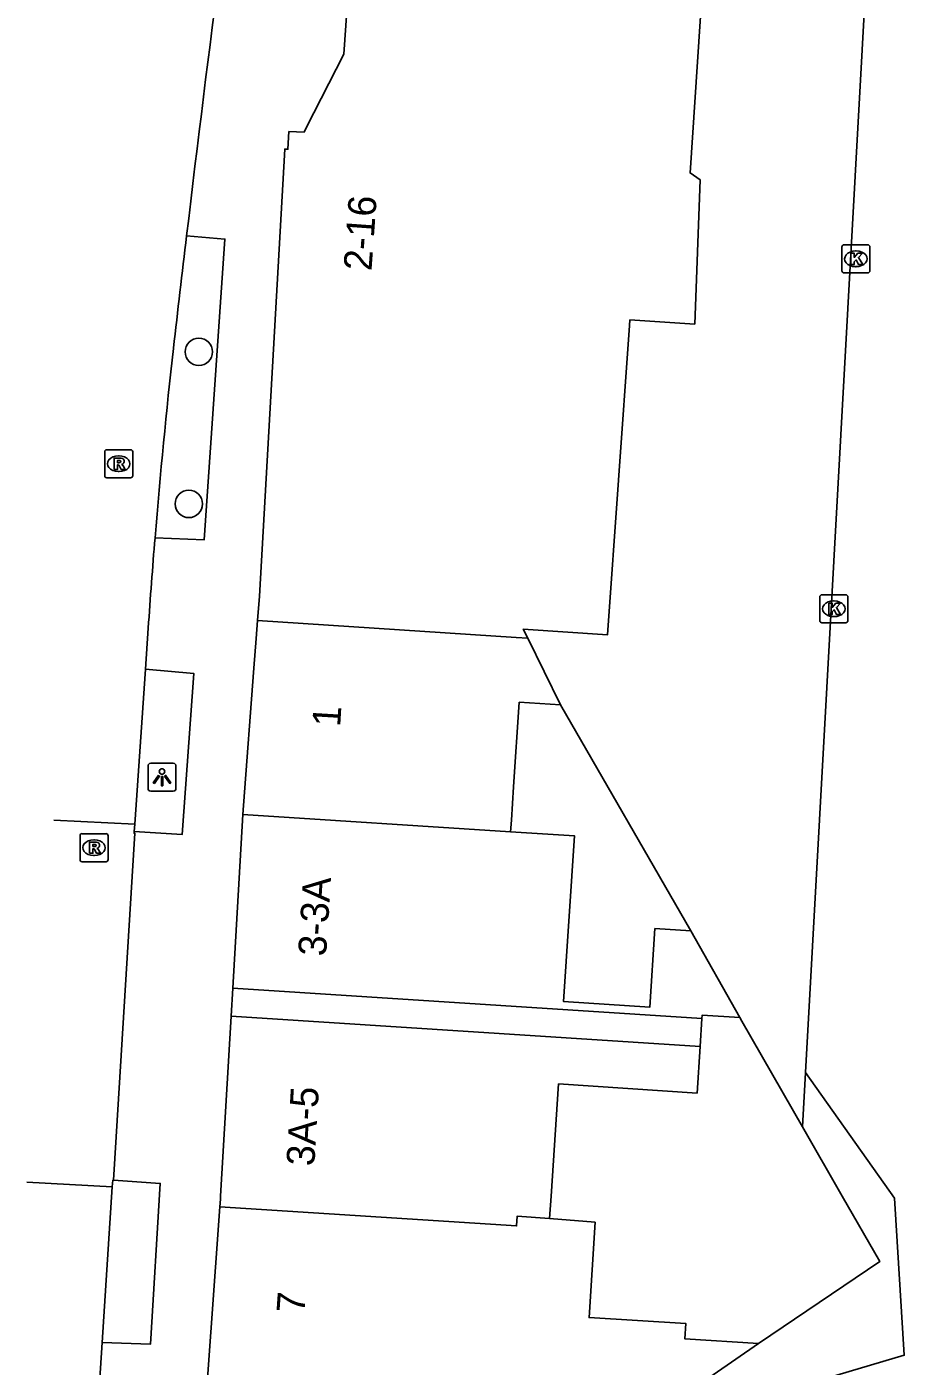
# Model space of a CAD drawing. Extents: x 161801 to 162379, y 382315 to 382832.
# Drawn here: x 161869.18 to 161900.49, y 382743.94 to 382791.72 of the extents above; entities that cross this region are included whole.
import ezdxf

# ---------------------------------------------------------------- set-up
doc = ezdxf.new("R2010")
doc.units = 0
for name, color, linetype in [('IMGEO_Boom', 7, 'Continuous'), ('IMGEO_Kolk', 7, 'Continuous'), ('IMGEO_Lichtpunt', 7, 'Continuous'), ('IMGEO_Pand', 7, 'Continuous'), ('IMGEO_Pand_nummerreeks', 7, 'Continuous'), ('IMGEO_Pand_overbouw', 7, 'Continuous'), ('IMGEO_Parkeervlak_open', 7, 'Continuous'), ('IMGEO_Rijbaan_lokaal_gesloten', 7, 'Continuous'), ('IMGEO_Rijbaan_lokaal_open', 7, 'Continuous'), ('IMGEO_Rioolput', 7, 'Continuous'), ('IMGEO_Voetpad_open', 7, 'Continuous')]:
    doc.layers.add(name, color=color, linetype=linetype)

msp = doc.modelspace()

# ---------------------------------------------------------------- linework, layer by layer
at = {"layer": 'IMGEO_Boom'}
for centre in [(161875.32, 382780.122), (161874.962, 382774.696)]:
    msp.add_circle(centre, 0.489, dxfattribs=at)
at = {"layer": 'IMGEO_Kolk'}
for p, q in [((161898.264, 382783.013), (161898.264, 382783.865)), ((161898.339, 382783.939), (161899.191, 382783.939)), ((161898.752, 382783.719), (161898.777, 382783.719)), ((161899.265, 382783.865), (161899.265, 382783.013)), ((161898.775, 382783.159), (161898.75, 382783.159)), ((161899.191, 382782.939), (161898.339, 382782.939)), ((161897.477, 382770.528), (161897.477, 382771.38)), ((161897.552, 382771.454), (161898.404, 382771.454)), ((161897.965, 382771.234), (161897.99, 382771.234)), ((161898.478, 382771.38), (161898.478, 382770.528)), ((161897.988, 382770.674), (161897.963, 382770.674)), ((161898.404, 382770.454), (161897.552, 382770.454))]:
    msp.add_line(p, q, dxfattribs=at)
for points in [[(161898.264, 382783.013), (161898.264, 382783.865)], [(161898.339, 382783.939), (161899.191, 382783.939)], [(161898.585, 382783.639), (161898.708, 382783.639), (161898.708, 382783.488), (161898.838, 382783.639), (161899.002, 382783.639), (161898.856, 382783.488), (161899.009, 382783.239), (161898.857, 382783.239), (161898.772, 382783.403), (161898.708, 382783.336), (161898.708, 382783.239), (161898.585, 382783.239), (161898.585, 382783.639)], [(161899.265, 382783.865), (161899.265, 382783.013)], [(161899.191, 382782.939), (161898.339, 382782.939)], [(161897.477, 382770.528), (161897.477, 382771.38)], [(161897.552, 382771.454), (161898.404, 382771.454)], [(161897.798, 382771.154), (161897.921, 382771.154), (161897.921, 382771.003), (161898.051, 382771.154), (161898.215, 382771.154), (161898.069, 382771.003), (161898.222, 382770.754), (161898.07, 382770.754), (161897.985, 382770.918), (161897.921, 382770.851), (161897.921, 382770.754), (161897.798, 382770.754), (161897.798, 382771.154)], [(161898.478, 382771.38), (161898.478, 382770.528)], [(161898.404, 382770.454), (161897.552, 382770.454)]]:
    msp.add_lwpolyline(points, dxfattribs=at)
for centre, start, end in [((161898.341, 382783.863), 91.552, 178.448), ((161898.341, 382783.863), 91.552, 178.448), ((161899.189, 382783.863), 1.552, 88.448), ((161899.189, 382783.863), 1.552, 88.448), ((161898.341, 382783.015), 181.552, 268.448), ((161898.341, 382783.015), 181.552, 268.448), ((161899.189, 382783.015), 271.552, 358.448), ((161899.189, 382783.015), 271.552, 358.448), ((161897.554, 382771.378), 91.552, 178.448), ((161897.554, 382771.378), 91.552, 178.448), ((161898.402, 382771.378), 1.552, 88.448), ((161898.402, 382771.378), 1.552, 88.448), ((161897.554, 382770.53), 181.552, 268.448), ((161897.554, 382770.53), 181.552, 268.448), ((161898.402, 382770.53), 271.552, 358.448), ((161898.402, 382770.53), 271.552, 358.448)]:
    msp.add_arc(centre, 0.0765, start, end, dxfattribs=at)
for centre, major_axis, ratio, start_param, end_param in [((161898.751, 382783.439), (-0.387, 0.002), 0.722429, 4.712389, 7.853982), ((161898.776, 382783.439), (-0.39, 0.002), 0.717154, 1.570796, 4.712389), ((161897.964, 382770.954), (-0.387, 0.002), 0.722429, 4.712389, 7.853982), ((161897.989, 382770.954), (-0.39, 0.002), 0.717154, 1.570796, 4.712389)]:
    msp.add_ellipse(centre, major_axis=major_axis, ratio=ratio, start_param=start_param, end_param=end_param, dxfattribs=at)
at = {"layer": 'IMGEO_Lichtpunt'}
for p, q in [((161873.507, 382765.351), (161873.507, 382764.544)), ((161873.507, 382765.351), (161873.507, 382764.544)), ((161874.409, 382765.446), (161873.601, 382765.446)), ((161874.409, 382765.446), (161873.601, 382765.446)), ((161874.503, 382764.544), (161874.503, 382765.351)), ((161874.503, 382764.544), (161874.503, 382765.351)), ((161873.601, 382764.45), (161874.409, 382764.45)), ((161873.601, 382764.45), (161874.409, 382764.45))]:
    msp.add_line(p, q, dxfattribs=at)
for points in [[(161873.881, 382765.015), (161873.92, 382764.987), (161873.732, 382764.725), (161873.694, 382764.752), (161873.881, 382765.015)], [(161873.983, 382764.967), (161874.03, 382764.967), (161874.03, 382764.645), (161873.983, 382764.645), (161873.983, 382764.967)], [(161874.093, 382764.987), (161874.131, 382765.014), (161874.318, 382764.752), (161874.279, 382764.724), (161874.093, 382764.987)]]:
    msp.add_lwpolyline(points, dxfattribs=at)
msp.add_circle((161874.006, 382765.149), 0.0994, dxfattribs=at)
for centre, start, end in [((161873.601, 382765.351), 90, 180), ((161873.601, 382765.351), 90, 180), ((161874.409, 382765.351), 0, 90), ((161874.409, 382765.351), 0, 90), ((161873.601, 382764.544), 180, 270), ((161873.601, 382764.544), 180, 270), ((161874.409, 382764.544), 270, 0), ((161874.409, 382764.544), 270, 360)]:
    msp.add_arc(centre, 0.0946, start, end, dxfattribs=at)
at = {"layer": 'IMGEO_Pand'}
for points in [[(161881.078, 382799.627), (161880.982, 382798.029), (161880.874, 382798.036), (161880.524, 382792.94), (161880.645, 382792.932), (161880.601, 382792.271), (161880.499, 382790.743), (161879.151, 382788.107), (161879.077, 382787.962), (161878.536, 382787.977), (161878.496, 382787.346), (161878.386, 382787.352), (161877.48, 382771.409), (161877.413, 382770.532)], [(161893.549, 382797.139), (161892.847, 382786.501), (161893.208, 382786.26), (161893.014, 382781.109), (161890.702, 382781.259), (161890.689, 382781.065), (161889.907, 382770.031), (161886.895, 382770.23), (161887.054, 382769.907)], [(161877.413, 382770.532), (161877.365, 382769.896), (161877.284, 382768.836), (161876.91, 382763.942), (161876.894, 382763.619)], [(161887.054, 382769.907), (161886.646, 382769.933), (161877.413, 382770.532)], [(161887.054, 382769.907), (161888.227, 382767.525)], [(161886.446, 382763.001), (161886.473, 382763.416), (161886.551, 382764.599), (161886.751, 382767.623), (161888.227, 382767.525)], [(161876.894, 382763.619), (161876.53, 382757.422)], [(161876.894, 382763.619), (161886.446, 382763.001)], [(161892.871, 382759.465), (161891.593, 382759.549), (161891.408, 382756.739), (161888.336, 382756.942), (161888.726, 382762.853), (161886.446, 382763.001)], [(161892.871, 382759.465), (161894.623, 382756.375)], [(161876.53, 382757.422), (161893.274, 382756.337), (161893.282, 382756.464), (161894.623, 382756.375)], [(161876.472, 382756.424), (161876.094, 382750), (161876.088, 382749.897), (161876.069, 382749.624)], [(161876.472, 382756.424), (161893.208, 382755.339), (161893.098, 382753.679), (161888.159, 382754.005), (161887.891, 382750), (161887.838, 382749.211)], [(161876.069, 382749.624), (161875.598, 382743.001)], [(161887.838, 382749.211), (161886.677, 382749.284), (161886.655, 382748.938), (161876.069, 382749.624)], [(161887.838, 382749.211), (161889.46, 382749.074), (161889.246, 382745.673), (161892.698, 382745.456), (161892.664, 382744.91), (161895.29, 382744.746)], [(161895.29, 382744.746), (161888.007, 382739.717)]]:
    msp.add_lwpolyline(points, dxfattribs=at)
at = {"layer": 'IMGEO_Pand_overbouw'}
msp.add_lwpolyline([(161876.53, 382757.422), (161876.472, 382756.424), (161893.208, 382755.339), (161893.274, 382756.337)], close=True, dxfattribs=at)
at = {"layer": 'IMGEO_Parkeervlak_open'}
for points in [[(161888.227, 382767.525), (161892.871, 382759.465)], [(161894.623, 382756.375), (161894.697, 382756.245), (161896.856, 382752.479)], [(161896.856, 382752.479), (161896.963, 382754.408)], [(161896.856, 382752.479), (161898.277, 382750), (161899.614, 382747.667), (161895.29, 382744.746)]]:
    msp.add_lwpolyline(points, dxfattribs=at)
at = {"layer": 'IMGEO_Rijbaan_lokaal_gesloten'}
for points in [[(161873.413, 382768.797), (161873.515, 382770.269)], [(161873.03, 382763.273), (161873.413, 382768.797)], [(161870.141, 382763.42), (161873.03, 382763.273)], [(161869.18, 382750.506), (161872.232, 382750.329)], [(161871.871, 382744.782), (161872.232, 382750.329)], [(161871.478, 382738.731), (161871.871, 382744.782)]]:
    msp.add_lwpolyline(points, dxfattribs=at)
for centre, radius, start, end in [((162782.42, 382676.474), 913.915, 171.975068, 173.226704), ((162692.058, 382686.795), 822.967, 173.198257, 173.479756), ((162099.263, 382754.97), 226.265, 173.58617, 175.30509), ((162089.643, 382755.65), 216.622, 175.27615, 176.13051)]:
    msp.add_arc(centre, radius, start, end, dxfattribs=at)
at = {"layer": 'IMGEO_Rijbaan_lokaal_open'}
for points in [[(161899.245, 382795.417), (161896.963, 382754.408)], [(161872.269, 382750.567), (161873.039, 382762.948), (161873.007, 382762.949), (161873.011, 382763.009)], [(161873.011, 382763.009), (161873.03, 382763.273)], [(161896.963, 382754.408), (161900.142, 382749.934), (161900.49, 382744.324), (161896.119, 382743.033), (161896.091, 382740.429), (161895.871, 382720.8)], [(161872.232, 382750.329), (161872.248, 382750.568), (161872.269, 382750.567)]]:
    msp.add_lwpolyline(points, dxfattribs=at)
at = {"layer": 'IMGEO_Rioolput'}
for p, q in [((161871.96, 382775.703), (161871.96, 382776.555)), ((161872.035, 382776.629), (161872.887, 382776.629)), ((161872.448, 382776.409), (161872.473, 382776.409)), ((161872.961, 382776.555), (161872.961, 382775.703)), ((161872.471, 382775.849), (161872.446, 382775.849)), ((161872.887, 382775.629), (161872.035, 382775.629)), ((161871.155, 382762.933), (161872.007, 382762.933)), ((161871.08, 382762.007), (161871.08, 382762.859)), ((161871.568, 382762.713), (161871.593, 382762.713)), ((161872.081, 382762.859), (161872.081, 382762.007)), ((161871.591, 382762.153), (161871.566, 382762.153)), ((161872.007, 382761.933), (161871.155, 382761.933))]:
    msp.add_line(p, q, dxfattribs=at)
for points in [[(161871.96, 382775.703), (161871.96, 382776.555)], [(161872.035, 382776.629), (161872.887, 382776.629)], [(161872.549, 382776.327), (161872.297, 382776.329), (161872.297, 382775.929)], [(161872.961, 382776.555), (161872.961, 382775.703)], [(161872.297, 382775.929), (161872.421, 382775.929), (161872.421, 382776.091), (161872.432, 382776.091)], [(161872.475, 382776.248), (161872.421, 382776.248), (161872.421, 382776.167)], [(161872.421, 382776.167), (161872.473, 382776.167)], [(161872.479, 382776.062), (161872.55, 382775.929), (161872.69, 382775.929), (161872.625, 382776.055)], [(161872.887, 382775.629), (161872.035, 382775.629)], [(161871.155, 382762.933), (161872.007, 382762.933)], [(161871.08, 382762.007), (161871.08, 382762.859)], [(161871.669, 382762.631), (161871.417, 382762.633), (161871.417, 382762.233)], [(161871.595, 382762.552), (161871.541, 382762.552), (161871.541, 382762.471)], [(161871.541, 382762.471), (161871.593, 382762.471)], [(161872.081, 382762.859), (161872.081, 382762.007)], [(161871.417, 382762.233), (161871.541, 382762.233), (161871.541, 382762.395), (161871.552, 382762.395)], [(161871.599, 382762.366), (161871.67, 382762.233), (161871.81, 382762.233), (161871.745, 382762.359)], [(161872.007, 382761.933), (161871.155, 382761.933)]]:
    msp.add_lwpolyline(points, dxfattribs=at)
for centre, radius, start, end in [((161872.037, 382776.553), 0.0765, 91.552, 178.448), ((161872.037, 382776.553), 0.0765, 91.552, 178.448), ((161872.548, 382776.217), 0.109, 350.3612, 89.416), ((161872.885, 382776.553), 0.0765, 1.552, 88.448), ((161872.885, 382776.553), 0.0765, 1.552, 88.448), ((161872.431, 382776.038), 0.0533, 26.0293, 88.6989), ((161872.457, 382776.356), 0.19, 274.7715, 282.9687), ((161872.481, 382776.152), 0.0964, 77.0061, 93.1865), ((161872.495, 382776.209), 0.0378, 276.6634, 79.6772), ((161872.546, 382776.217), 0.112, 277.5842, 350.9817), ((161872.53, 382776.002), 0.108, 29.5134, 73.7905), ((161872.037, 382775.705), 0.0765, 181.552, 268.448), ((161872.037, 382775.705), 0.0765, 181.552, 268.448), ((161872.885, 382775.705), 0.0765, 271.552, 358.448), ((161872.885, 382775.705), 0.0765, 271.552, 358.448), ((161871.157, 382762.857), 0.0765, 91.552, 178.448), ((161871.157, 382762.857), 0.0765, 91.552, 178.448), ((161872.005, 382762.857), 0.0765, 1.552, 88.448), ((161872.005, 382762.857), 0.0765, 1.552, 88.448), ((161871.577, 382762.66), 0.19, 274.7715, 282.9687), ((161871.601, 382762.456), 0.0964, 77.0061, 93.1865), ((161871.615, 382762.513), 0.0378, 276.6634, 79.6772), ((161871.668, 382762.521), 0.109, 350.3612, 89.416), ((161871.666, 382762.521), 0.112, 277.5842, 350.9817), ((161871.157, 382762.009), 0.0765, 181.552, 268.448), ((161871.157, 382762.009), 0.0765, 181.552, 268.448), ((161871.551, 382762.342), 0.0533, 26.0293, 88.6989), ((161871.65, 382762.306), 0.108, 29.5134, 73.7905), ((161872.005, 382762.009), 0.0765, 271.552, 358.448), ((161872.005, 382762.009), 0.0765, 271.552, 358.448)]:
    msp.add_arc(centre, radius, start, end, dxfattribs=at)
for centre, major_axis, ratio, start_param, end_param in [((161872.447, 382776.129), (-0.387, 0.002), 0.722429, 4.712389, 7.853982), ((161872.472, 382776.129), (-0.39, 0.002), 0.717154, 1.570796, 4.712389), ((161871.567, 382762.433), (-0.387, 0.002), 0.722429, 4.712389, 7.853982), ((161871.592, 382762.433), (-0.39, 0.002), 0.717154, 1.570796, 4.712389)]:
    msp.add_ellipse(centre, major_axis=major_axis, ratio=ratio, start_param=start_param, end_param=end_param, dxfattribs=at)
at = {"layer": 'IMGEO_Voetpad_open'}
for points in [[(161873.757, 382773.49), (161875.514, 382773.419), (161876.252, 382784.141), (161874.883, 382784.262)], [(161873.011, 382763.009), (161874.719, 382762.9), (161875.146, 382768.641), (161873.413, 382768.797)], [(161876.53, 382757.422), (161876.472, 382756.424)], [(161871.871, 382744.782), (161873.589, 382744.72), (161873.944, 382750.456), (161872.269, 382750.567)]]:
    msp.add_lwpolyline(points, dxfattribs=at)

# ---------------------------------------------------------------- texts
at = {"layer": 'IMGEO_Pand_nummerreeks'}
for s, rotation, p in [('2-16', 85.9093, (161881.48, 382782.99)), ('1', 86.6369, (161880.363, 382766.726)), ('3-3A', 86.3734, (161879.858, 382758.542)), ('3A-5', 86.6085, (161879.439, 382751.059)), ('7', 85.9322, (161879.086, 382745.805))]:
    msp.add_text(s, height=1, rotation=rotation, dxfattribs=at).set_placement(p)

doc.saveas('drawing.dxf')
